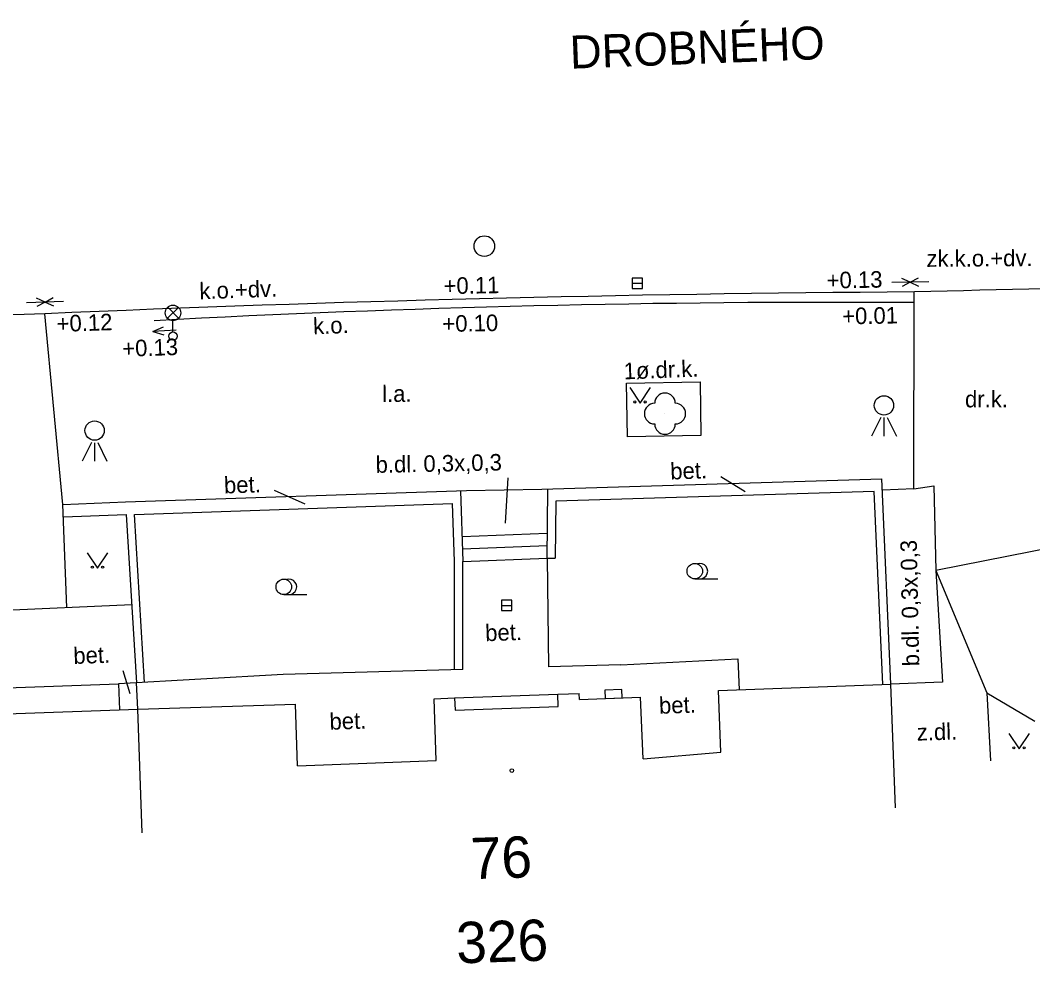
# Model space of a CAD drawing. Extents: x -597862 to -597276, y -1159156 to -1158889.
# Drawn here: x -597722.63 to -597698.08, y -1159091.84 to -1159068.97 of the extents above; entities that cross this region are included whole.
import ezdxf

# ---------------------------------------------------------------- set-up
doc = ezdxf.new("R2010")
doc.units = 0
for name, color, linetype in [('Vrstva 14', 7, 'Continuous'), ('Vrstva 15', 7, 'Continuous'), ('Vrstva 25', 7, 'Continuous'), ('Vrstva 29', 7, 'Continuous'), ('Vrstva 4', 7, 'Continuous'), ('Vrstva 42', 7, 'Continuous'), ('Vrstva 43', 7, 'Continuous'), ('Vrstva 44', 7, 'Continuous'), ('Vrstva 49', 7, 'Continuous'), ('Vrstva 5', 7, 'Continuous'), ('Vrstva 50', 7, 'Continuous'), ('Vrstva 7', 7, 'Continuous')]:
    doc.layers.add(name, color=color, linetype=linetype)

msp = doc.modelspace()

# ---------------------------------------------------------------- linework, layer by layer
at = {"layer": 'Vrstva 14'}
for p, q in [((-597706.278, -1159082.516), (-597705.716, -1159082.516)), ((-597716.243, -1159082.897), (-597715.681, -1159082.897))]:
    msp.add_line(p, q, dxfattribs=at)
for points in [[(-597707.855, -1159077.877), (-597707.605, -1159078.252), (-597707.355, -1159077.877)], [(-597721.01, -1159081.883), (-597720.76, -1159082.258), (-597720.51, -1159081.883)], [(-597698.665, -1159086.261), (-597698.415, -1159086.636), (-597698.165, -1159086.261)]]:
    msp.add_lwpolyline(points, dxfattribs=at)
for centre, radius in [((-597707.73, -1159078.227), 0.025), ((-597707.48, -1159078.227), 0.025), ((-597707, -1159078.51), 0.00025), ((-597706.278, -1159082.328), 0.188), ((-597720.885, -1159082.233), 0.025), ((-597720.635, -1159082.233), 0.025), ((-597716.243, -1159082.709), 0.188), ((-597698.54, -1159086.611), 0.025), ((-597698.29, -1159086.611), 0.025)]:
    msp.add_circle(centre, radius, dxfattribs=at)
for centre, radius, start, end in [((-597707, -1159078.26), 0.25, 0, 180), ((-597707.25, -1159078.51), 0.25, 90, 270), ((-597706.75, -1159078.51), 0.25, 270, 90), ((-597707, -1159078.76), 0.25, 180, 360), ((-597706.153, -1159082.328), 0.188, 249.4944, 109.0474), ((-597716.118, -1159082.709), 0.188, 249.4944, 109.0474)]:
    msp.add_arc(centre, radius, start, end, dxfattribs=at)
at = {"layer": 'Vrstva 15'}
for points in [[(-597711.921, -1159081.49), (-597709.853, -1159081.409)], [(-597711.911, -1159081.79), (-597709.856, -1159081.709)], [(-597711.9, -1159082.09), (-597709.86, -1159082.01)]]:
    msp.add_lwpolyline(points, dxfattribs=at)
msp.add_circle((-597710.714, -1159087.161), 0.0438, dxfattribs=at)
at = {"layer": 'Vrstva 25'}
for p, q in [((-597707.795, -1159075.35), (-597707.545, -1159075.35)), ((-597710.965, -1159083.16), (-597710.715, -1159083.16))]:
    msp.add_line(p, q, dxfattribs=at)
for points in [[(-597707.795, -1159075.475), (-597707.545, -1159075.475), (-597707.545, -1159075.225), (-597707.795, -1159075.225)], [(-597710.965, -1159083.285), (-597710.715, -1159083.285), (-597710.715, -1159083.035), (-597710.965, -1159083.035)]]:
    msp.add_lwpolyline(points, close=True, dxfattribs=at)
msp.add_circle((-597711.38, -1159074.45), 0.25, dxfattribs=at)
at = {"layer": 'Vrstva 29'}
for p, q in [((-597719.062, -1159076.199), (-597718.798, -1159075.935)), ((-597718.794, -1159076.198), (-597719.058, -1159075.933)), ((-597718.93, -1159076.53), (-597718.93, -1159076.255))]:
    msp.add_line(p, q, dxfattribs=at)
msp.add_lwpolyline([(-597708.452, -1159085.415), (-597708.038, -1159085.398), (-597708.046, -1159085.193), (-597708.46, -1159085.21)], close=True, dxfattribs=at)
for centre, radius in [((-597718.93, -1159076.068), 0.188), ((-597718.93, -1159076.63), 0.1)]:
    msp.add_circle(centre, radius, dxfattribs=at)
at = {"layer": 'Vrstva 4'}
for p, q in [((-597705.7, -1159085.22), (-597701.52, -1159085.07)), ((-597701.412, -1159088.068), (-597701.52, -1159085.07)), ((-597712.1, -1159085.402), (-597709.6, -1159085.309)), ((-597709.6, -1159085.309), (-597709.08, -1159085.29)), ((-597709.588, -1159085.609), (-597709.6, -1159085.31)), ((-597709.075, -1159085.44), (-597709.08, -1159085.29)), ((-597709.075, -1159085.44), (-597707.59, -1159085.38)), ((-597707.529, -1159086.879), (-597707.59, -1159085.38)), ((-597705.646, -1159086.719), (-597705.7, -1159085.22)), ((-597719.78, -1159085.67), (-597715.96, -1159085.55)), ((-597715.913, -1159087.049), (-597715.96, -1159085.55)), ((-597712.6, -1159085.42), (-597712.1, -1159085.402)), ((-597712.545, -1159086.919), (-597712.6, -1159085.42)), ((-597712.1, -1159085.402), (-597712.088, -1159085.701)), ((-597723.69, -1159085.81), (-597719.78, -1159085.67)), ((-597719.673, -1159088.668), (-597719.78, -1159085.67)), ((-597707.529, -1159086.879), (-597705.646, -1159086.719)), ((-597715.913, -1159087.049), (-597712.545, -1159086.919))]:
    msp.add_line(p, q, dxfattribs=at)
at = {"layer": 'Vrstva 44'}
for p, q in [((-597701.764, -1159078.603), (-597701.99, -1159079.055)), ((-597701.69, -1159078.605), (-597701.69, -1159079.055)), ((-597701.615, -1159078.603), (-597701.39, -1159079.055)), ((-597720.904, -1159079.213), (-597721.13, -1159079.665)), ((-597720.83, -1159079.215), (-597720.83, -1159079.665)), ((-597720.755, -1159079.213), (-597720.53, -1159079.665))]:
    msp.add_line(p, q, dxfattribs=at)
for centre in [(-597701.69, -1159078.31), (-597720.83, -1159078.92)]:
    msp.add_circle(centre, 0.234, dxfattribs=at)
at = {"layer": 'Vrstva 49'}
for p, q in [((-597700.602, -1159075.311), (-597701.502, -1159075.335)), ((-597701.052, -1159075.323), (-597701.255, -1159075.231)), ((-597701.052, -1159075.323), (-597701.251, -1159075.428)), ((-597701.052, -1159075.323), (-597700.856, -1159075.217)), ((-597701.052, -1159075.323), (-597700.852, -1159075.417)), ((-597721.581, -1159075.788), (-597722.481, -1159075.82)), ((-597722.031, -1159075.804), (-597722.235, -1159075.714)), ((-597722.031, -1159075.804), (-597722.229, -1159075.91)), ((-597722.031, -1159075.804), (-597721.835, -1159075.697)), ((-597722.031, -1159075.804), (-597721.83, -1159075.897)), ((-597719.419, -1159076.516), (-597719.16, -1159076.405)), ((-597718.856, -1159076.487), (-597719.419, -1159076.516)), ((-597719.419, -1159076.516), (-597719.148, -1159076.597)), ((-597710.81, -1159080.062), (-597710.873, -1159081.164)), ((-597705.647, -1159080.037), (-597705.056, -1159080.396)), ((-597716.477, -1159080.362), (-597715.735, -1159080.694)), ((-597720.145, -1159084.733), (-597719.974, -1159085.296))]:
    msp.add_line(p, q, dxfattribs=at)
at = {"layer": 'Vrstva 5'}
msp.add_line((-597712.088, -1159085.701), (-597709.588, -1159085.609), dxfattribs=at)
at = {"layer": 'Vrstva 7'}
for p, q in [((-597700.97, -1159080.33), (-597700.959, -1159075.56)), ((-597721.6, -1159080.71), (-597722.04, -1159076.09)), ((-597707.93, -1159077.77), (-597706.15, -1159077.74)), ((-597707.908, -1159079.07), (-597707.93, -1159077.77)), ((-597706.15, -1159077.74), (-597706.128, -1159079.04)), ((-597706.128, -1159079.04), (-597707.908, -1159079.07)), ((-597709.989, -1159080.344), (-597701.74, -1159080.09)), ((-597701.52, -1159085.07), (-597701.74, -1159080.09)), ((-597720.08, -1159080.65), (-597711.811, -1159080.376)), ((-597711.96, -1159080.38), (-597711.9, -1159082.09)), ((-597711.811, -1159080.376), (-597709.989, -1159080.344)), ((-597709.86, -1159082.01), (-597709.84, -1159080.34)), ((-597701.72, -1159085.077), (-597701.927, -1159080.396)), ((-597700.97, -1159080.33), (-597701.728, -1159080.363)), ((-597700.97, -1159080.33), (-597700.48, -1159080.26)), ((-597700.48, -1159080.26), (-597700.43, -1159082.31)), ((-597721.6, -1159080.71), (-597720.08, -1159080.65)), ((-597721.501, -1159083.208), (-597721.6, -1159080.71)), ((-597719.862, -1159080.951), (-597712.149, -1159080.688)), ((-597709.644, -1159080.634), (-597709.66, -1159082.012)), ((-597721.588, -1159081.01), (-597720.062, -1159080.958)), ((-597720.062, -1159080.958), (-597719.817, -1159085.035)), ((-597719.617, -1159085.024), (-597719.862, -1159080.951)), ((-597696.68, -1159081.57), (-597700.43, -1159082.31)), ((-597711.9, -1159084.708), (-597711.9, -1159082.09)), ((-597709.86, -1159082.01), (-597709.66, -1159082.012)), ((-597709.86, -1159082.01), (-597709.828, -1159084.649)), ((-597700.43, -1159082.31), (-597699.2, -1159085.28)), ((-597700.43, -1159082.31), (-597700.27, -1159085.02)), ((-597725.208, -1159083.368), (-597719.931, -1159083.14)), ((-597708.07, -1159084.6), (-597705.23, -1159084.45)), ((-597705.23, -1159084.45), (-597705.203, -1159085.202)), ((-597727.702, -1159085.326), (-597720.25, -1159085.059)), ((-597720.25, -1159085.06), (-597720.228, -1159085.686)), ((-597719.78, -1159085.67), (-597719.817, -1159085.035)), ((-597700.27, -1159085.02), (-597701.52, -1159085.07)), ((-597699.2, -1159085.28), (-597698.03, -1159085.96)), ((-597699.2, -1159085.28), (-597699.109, -1159086.928))]:
    msp.add_line(p, q, dxfattribs=at)
for points in [[(-597701.927, -1159080.396), (-597709.644, -1159080.634)], [(-597712.1, -1159084.713), (-597712.1, -1159082.094), (-597712.149, -1159080.688)], [(-597708.07, -1159084.6), (-597709.828, -1159084.649)], [(-597711.9, -1159084.708), (-597716.26, -1159084.83), (-597720.25, -1159085.06)]]:
    msp.add_lwpolyline(points, dxfattribs=at)
for centre, radius, start, end in [((-597647.735, -1161198.193), 2123.3, 91.093878, 91.436122), ((-597697.179, -1159645.513), 569.966, 90.37913, 92.49999), ((-597702.959, -1159378.273), 302.46, 89.62124, 93.11402), ((-597714.654, -1159355.996), 280.003, 91.51148, 94.7642)]:
    msp.add_arc(centre, radius, start, end, dxfattribs=at)

# ---------------------------------------------------------------- texts
at = {"layer": 'Vrstva 42'}
msp.add_text('DROBNÉHO', height=0.8, rotation=2.1962, dxfattribs=at).set_placement((-597709.293, -1159070.15))
at = {"layer": 'Vrstva 43'}
for s, p in [('76', (-597711.697, -1159089.795)), ('326', (-597712.048, -1159091.837))]:
    msp.add_text(s, height=1, rotation=1.882, dxfattribs=at).set_placement(p)
at = {"layer": 'Vrstva 49'}
for s, rotation, p in [('zk.k.o.+dv.', 0.4149, (-597700.658, -1159074.952)), ('k.o.+dv.', 2.0084, (-597718.283, -1159075.738)), ('k.o.', 2.3859, (-597715.525, -1159076.589)), ('1ø.dr.k.', 2.1569, (-597707.996, -1159077.68)), ('l.a.', 0.4195, (-597713.857, -1159078.228)), ('dr.k.', 359.9512, (-597699.725, -1159078.357)), ('b.dl. 0,3x,0,3', 1.1293, (-597714.013, -1159079.946)), ('bet.', 1.9942, (-597706.866, -1159080.108)), ('bet.', 1.9942, (-597717.687, -1159080.447)), ('b.dl. 0,3x,0,3', 91.1293, (-597700.834, -1159084.63)), ('bet.', 1.9942, (-597711.353, -1159084.027)), ('bet.', 1.9942, (-597721.34, -1159084.578)), ('bet.', 1.9942, (-597707.139, -1159085.787)), ('bet.', 1.9942, (-597715.128, -1159086.174)), ('z.dl.', 1.6542, (-597700.89, -1159086.436))]:
    msp.add_text(s, height=0.4, rotation=rotation, dxfattribs=at).set_placement(p)
at = {"layer": 'Vrstva 50'}
for s, rotation, p in [('+0.13', 1.0366, (-597703.077, -1159075.478)), ('+0.11', 1.0366, (-597712.366, -1159075.613)), ('+0.01', 1.0366, (-597702.7, -1159076.347)), ('+0.12', 1.9464, (-597721.745, -1159076.531)), ('+0.10', 1.0366, (-597712.394, -1159076.531)), ('+0.13', 1.9464, (-597720.153, -1159077.133))]:
    msp.add_text(s, height=0.4, rotation=rotation, dxfattribs=at).set_placement(p)

doc.saveas('drawing.dxf')
